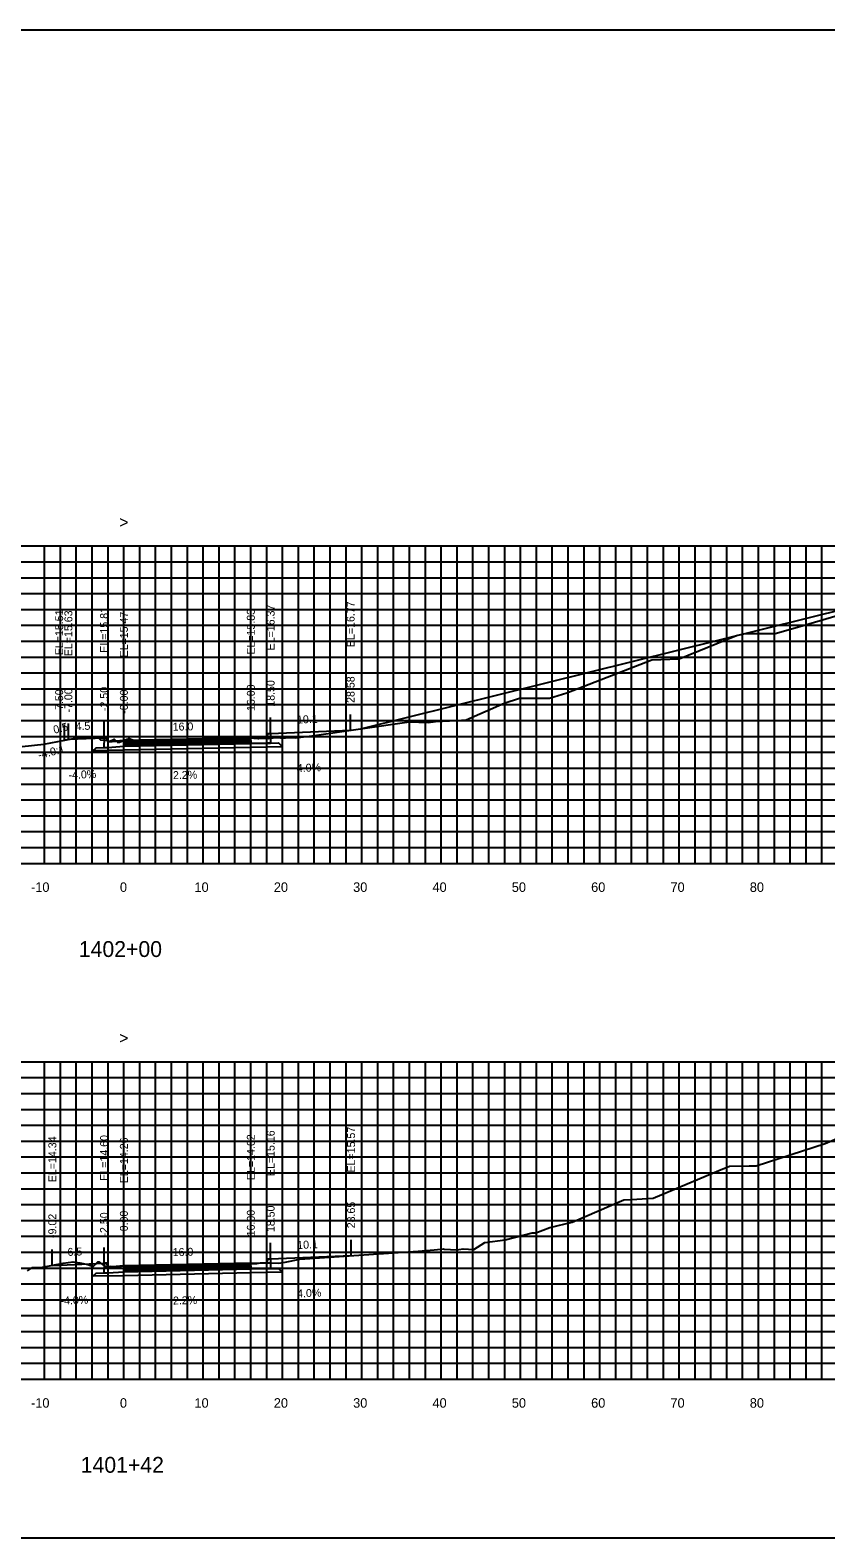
# Model space of a CAD drawing. Extents: x 1797652 to 1804159, y 242516 to 246906.
# Drawn here: x 1802292.7 to 1802393, y 242516 to 242706 of the extents above; entities that cross this region are included whole.
import ezdxf

# ---------------------------------------------------------------- set-up
doc = ezdxf.new("R2010")
doc.units = 0
for name, color, linetype in [('1', 7, 'Continuous'), ('10', 7, 'Continuous'), ('2', 7, 'Continuous'), ('3', 7, 'Continuous'), ('4', 7, 'Continuous'), ('60', 7, 'Continuous'), ('BASE', 7, 'Continuous'), ('CL-CNST', 7, 'Continuous'), ('Level 62', 7, 'Continuous'), ('LOWER BINDER', 7, 'Continuous'), ('M-ROADS', 7, 'Continuous'), ('UPPER BINDER', 7, 'Continuous')]:
    doc.layers.add(name, color=color, linetype=linetype)

msp = doc.modelspace()

# ---------------------------------------------------------------- linework, layer by layer
for p, q in [((1802297.49, 242616.64), (1802297.49, 242618.64)), ((1802301.99, 242616.82), (1802301.99, 242618.82)), ((1802320.49, 242616.83), (1802320.49, 242618.83)), ((1802322.99, 242617.37), (1802322.99, 242619.37)), ((1802333.07, 242617.77), (1802333.07, 242619.77)), ((1802296.99, 242616.51), (1802296.99, 242618.51)), ((1802304.49, 242616.48), (1802304.49, 242618.48)), ((1802295.47, 242550.34), (1802295.47, 242552.34)), ((1802301.99, 242550.6), (1802301.99, 242552.6)), ((1802304.49, 242550.26), (1802304.49, 242552.26)), ((1802320.49, 242550.62), (1802320.49, 242552.62)), ((1802322.99, 242551.16), (1802322.99, 242553.16)), ((1802333.13, 242551.57), (1802333.13, 242553.57))]:
    msp.add_line(p, q)
for points in [[(1802154.49, 242516), (1802454.49, 242516), (1802454.49, 242706), (1802154.49, 242706)], [(1802304.49, 242616.48), (1802302.49, 242616.32), (1802302.32, 242616.82), (1802301.99, 242616.82), (1802301.98, 242615.59), (1802302.48, 242615.59), (1802304.49, 242615.76)], [(1802320.49, 242616.83), (1802322.49, 242616.87), (1802322.66, 242617.37), (1802322.99, 242617.37), (1802322.99, 242616.15), (1802322.49, 242616.15), (1802320.49, 242616.11)], [(1802304.49, 242550.26), (1802302.49, 242550.1), (1802302.32, 242550.6), (1802301.99, 242550.6), (1802301.98, 242549.38), (1802302.48, 242549.38), (1802304.49, 242549.54)], [(1802320.49, 242550.62), (1802322.49, 242550.66), (1802322.66, 242551.16), (1802322.99, 242551.16), (1802322.99, 242549.94), (1802322.49, 242549.94), (1802320.49, 242549.9)]]:
    msp.add_lwpolyline(points, close=True)
at = {"layer": '2'}
for points in [[(1802320.49, 242616.68), (1802320.49, 242616.83), (1802304.49, 242616.48), (1802304.49, 242616.33)], [(1802320.49, 242550.47), (1802320.49, 242550.62), (1802304.49, 242550.26), (1802304.49, 242550.11)]]:
    msp.add_lwpolyline(points, close=True, dxfattribs=at)
at = {"layer": '60'}
for p, q in [((1802154.49, 242601), (1802454.49, 242601)), ((1802294.49, 242600.94), (1802294.49, 242601)), ((1802304.49, 242600.94), (1802304.49, 242601)), ((1802314.49, 242600.94), (1802314.49, 242601)), ((1802324.49, 242600.94), (1802324.49, 242601)), ((1802334.49, 242600.94), (1802334.49, 242601)), ((1802344.49, 242600.94), (1802344.49, 242601)), ((1802354.49, 242600.94), (1802354.49, 242601)), ((1802364.49, 242600.94), (1802364.49, 242601)), ((1802374.49, 242600.94), (1802374.49, 242601)), ((1802384.49, 242600.94), (1802384.49, 242601)), ((1802154.49, 242536), (1802454.49, 242536)), ((1802294.49, 242535.94), (1802294.49, 242536)), ((1802304.49, 242535.94), (1802304.49, 242536)), ((1802314.49, 242535.94), (1802314.49, 242536)), ((1802324.49, 242535.94), (1802324.49, 242536)), ((1802334.49, 242535.94), (1802334.49, 242536)), ((1802344.49, 242535.94), (1802344.49, 242536)), ((1802354.49, 242535.94), (1802354.49, 242536)), ((1802364.49, 242535.94), (1802364.49, 242536)), ((1802374.49, 242535.94), (1802374.49, 242536)), ((1802384.49, 242535.94), (1802384.49, 242536))]:
    msp.add_line(p, q, dxfattribs=at)
at = {"layer": 'BASE'}
for points in [[(1802304.49, 242615.76), (1802320.49, 242616.11), (1802322.49, 242616.15), (1802322.99, 242616.15), (1802323.99, 242616.17), (1802324.47, 242615.69), (1802320.49, 242615.61), (1802304.49, 242615.26), (1802300.58, 242615.17), (1802300.98, 242615.57), (1802301.98, 242615.59), (1802302.48, 242615.59)], [(1802304.49, 242549.54), (1802320.49, 242549.9), (1802322.49, 242549.94), (1802322.99, 242549.94), (1802323.99, 242549.96), (1802324.47, 242549.48), (1802320.49, 242549.4), (1802304.49, 242549.04), (1802300.58, 242548.96), (1802300.98, 242549.36), (1802301.98, 242549.38), (1802302.48, 242549.38)]]:
    msp.add_lwpolyline(points, close=True, dxfattribs=at)
at = {"layer": 'CL-CNST'}
for points in [[(1802334.54, 242617.99), (1802357.55, 242623.69), (1802395.98, 242633.23), (1802397.78, 242633.68), (1802399.36, 242633.75), (1802399.8, 242633.77), (1802406.48, 242634.07), (1802408.79, 242634.18), (1802408.81, 242634.2), (1802408.87, 242634.25), (1802409.6, 242634.28), (1802409.88, 242634.29), (1802413.4, 242634.45), (1802421.97, 242634.84), (1802429.53, 242635.19), (1802434.07, 242635.39), (1802439.18, 242635.63), (1802446.16, 242635.94), (1802452.06, 242636.21), (1802454.49, 242636.32)], [(1802296.99, 242616.51), (1802297.49, 242616.64), (1802301.99, 242616.82), (1802302.32, 242616.82), (1802302.49, 242616.32), (1802304.49, 242616.48), (1802320.49, 242616.83), (1802322.49, 242616.87), (1802322.66, 242617.37), (1802322.99, 242617.37), (1802333.07, 242617.77)], [(1802295.47, 242550.34), (1802301.99, 242550.6), (1802302.32, 242550.6), (1802302.49, 242550.1), (1802304.49, 242550.26), (1802320.49, 242550.62), (1802322.49, 242550.66), (1802322.66, 242551.16), (1802322.99, 242551.16), (1802333.13, 242551.57)]]:
    msp.add_lwpolyline(points, dxfattribs=at)
at = {"layer": 'Level 62'}
for p, q in [((1802154.49, 242641), (1802454.49, 242641)), ((1802294.49, 242601), (1802294.49, 242641)), ((1802296.49, 242601), (1802296.49, 242641)), ((1802298.49, 242601), (1802298.49, 242641)), ((1802300.49, 242601), (1802300.49, 242641)), ((1802302.49, 242601), (1802302.49, 242641)), ((1802304.49, 242601), (1802304.49, 242641)), ((1802306.49, 242601), (1802306.49, 242641)), ((1802308.49, 242601), (1802308.49, 242641)), ((1802310.49, 242601), (1802310.49, 242641)), ((1802312.49, 242601), (1802312.49, 242641)), ((1802314.49, 242601), (1802314.49, 242641)), ((1802316.49, 242601), (1802316.49, 242641)), ((1802318.49, 242601), (1802318.49, 242641)), ((1802320.49, 242601), (1802320.49, 242641)), ((1802322.49, 242601), (1802322.49, 242641)), ((1802324.49, 242601), (1802324.49, 242641)), ((1802326.49, 242601), (1802326.49, 242641)), ((1802328.49, 242601), (1802328.49, 242641)), ((1802330.49, 242601), (1802330.49, 242641)), ((1802332.49, 242601), (1802332.49, 242641)), ((1802334.49, 242601), (1802334.49, 242641)), ((1802336.49, 242601), (1802336.49, 242641)), ((1802338.49, 242601), (1802338.49, 242641)), ((1802340.49, 242601), (1802340.49, 242641)), ((1802342.49, 242601), (1802342.49, 242641)), ((1802344.49, 242601), (1802344.49, 242641)), ((1802346.49, 242601), (1802346.49, 242641)), ((1802348.49, 242601), (1802348.49, 242641)), ((1802350.49, 242601), (1802350.49, 242641)), ((1802352.49, 242601), (1802352.49, 242641)), ((1802354.49, 242601), (1802354.49, 242641)), ((1802356.49, 242601), (1802356.49, 242641)), ((1802358.49, 242601), (1802358.49, 242641)), ((1802360.49, 242601), (1802360.49, 242641)), ((1802362.49, 242601), (1802362.49, 242641)), ((1802364.49, 242601), (1802364.49, 242641)), ((1802366.49, 242601), (1802366.49, 242641)), ((1802368.49, 242601), (1802368.49, 242641)), ((1802370.49, 242601), (1802370.49, 242641)), ((1802372.49, 242601), (1802372.49, 242641)), ((1802374.49, 242601), (1802374.49, 242641)), ((1802376.49, 242601), (1802376.49, 242641)), ((1802378.49, 242601), (1802378.49, 242641)), ((1802380.49, 242601), (1802380.49, 242641)), ((1802382.49, 242601), (1802382.49, 242641)), ((1802384.49, 242601), (1802384.49, 242641)), ((1802386.49, 242601), (1802386.49, 242641)), ((1802388.49, 242601), (1802388.49, 242641)), ((1802390.49, 242601), (1802390.49, 242641)), ((1802392.49, 242601), (1802392.49, 242641)), ((1802154.49, 242639), (1802454.49, 242639)), ((1802154.49, 242637), (1802454.49, 242637)), ((1802154.49, 242635), (1802454.49, 242635)), ((1802154.49, 242633), (1802454.49, 242633)), ((1802154.49, 242631), (1802454.49, 242631)), ((1802154.49, 242629), (1802454.49, 242629)), ((1802154.49, 242627), (1802454.49, 242627)), ((1802154.49, 242625), (1802454.49, 242625)), ((1802154.49, 242623), (1802454.49, 242623)), ((1802154.49, 242621), (1802454.49, 242621)), ((1802154.49, 242619), (1802454.49, 242619)), ((1802154.49, 242617), (1802454.49, 242617)), ((1802154.49, 242615), (1802454.49, 242615)), ((1802154.49, 242613), (1802454.49, 242613)), ((1802154.49, 242611), (1802454.49, 242611)), ((1802154.49, 242609), (1802454.49, 242609)), ((1802154.49, 242607), (1802454.49, 242607)), ((1802154.49, 242605), (1802454.49, 242605)), ((1802154.49, 242603), (1802454.49, 242603)), ((1802154.49, 242601), (1802454.49, 242601)), ((1802154.49, 242576), (1802454.49, 242576)), ((1802294.49, 242536), (1802294.49, 242576)), ((1802296.49, 242536), (1802296.49, 242576)), ((1802298.49, 242536), (1802298.49, 242576)), ((1802300.49, 242536), (1802300.49, 242576)), ((1802302.49, 242536), (1802302.49, 242576)), ((1802304.49, 242536), (1802304.49, 242576)), ((1802306.49, 242536), (1802306.49, 242576)), ((1802308.49, 242536), (1802308.49, 242576)), ((1802310.49, 242536), (1802310.49, 242576)), ((1802312.49, 242536), (1802312.49, 242576)), ((1802314.49, 242536), (1802314.49, 242576)), ((1802316.49, 242536), (1802316.49, 242576)), ((1802318.49, 242536), (1802318.49, 242576)), ((1802320.49, 242536), (1802320.49, 242576)), ((1802322.49, 242536), (1802322.49, 242576)), ((1802324.49, 242536), (1802324.49, 242576)), ((1802326.49, 242536), (1802326.49, 242576)), ((1802328.49, 242536), (1802328.49, 242576)), ((1802330.49, 242536), (1802330.49, 242576)), ((1802332.49, 242536), (1802332.49, 242576)), ((1802334.49, 242536), (1802334.49, 242576)), ((1802336.49, 242536), (1802336.49, 242576)), ((1802338.49, 242536), (1802338.49, 242576)), ((1802340.49, 242536), (1802340.49, 242576)), ((1802342.49, 242536), (1802342.49, 242576)), ((1802344.49, 242536), (1802344.49, 242576)), ((1802346.49, 242536), (1802346.49, 242576)), ((1802348.49, 242536), (1802348.49, 242576)), ((1802350.49, 242536), (1802350.49, 242576)), ((1802352.49, 242536), (1802352.49, 242576)), ((1802354.49, 242536), (1802354.49, 242576)), ((1802356.49, 242536), (1802356.49, 242576)), ((1802358.49, 242536), (1802358.49, 242576)), ((1802360.49, 242536), (1802360.49, 242576)), ((1802362.49, 242536), (1802362.49, 242576)), ((1802364.49, 242536), (1802364.49, 242576)), ((1802366.49, 242536), (1802366.49, 242576)), ((1802368.49, 242536), (1802368.49, 242576)), ((1802370.49, 242536), (1802370.49, 242576)), ((1802372.49, 242536), (1802372.49, 242576)), ((1802374.49, 242536), (1802374.49, 242576)), ((1802376.49, 242536), (1802376.49, 242576)), ((1802378.49, 242536), (1802378.49, 242576)), ((1802380.49, 242536), (1802380.49, 242576)), ((1802382.49, 242536), (1802382.49, 242576)), ((1802384.49, 242536), (1802384.49, 242576)), ((1802386.49, 242536), (1802386.49, 242576)), ((1802388.49, 242536), (1802388.49, 242576)), ((1802390.49, 242536), (1802390.49, 242576)), ((1802392.49, 242536), (1802392.49, 242576)), ((1802154.49, 242574), (1802454.49, 242574)), ((1802154.49, 242572), (1802454.49, 242572)), ((1802154.49, 242570), (1802454.49, 242570)), ((1802154.49, 242568), (1802454.49, 242568)), ((1802154.49, 242566), (1802454.49, 242566)), ((1802154.49, 242564), (1802454.49, 242564)), ((1802154.49, 242562), (1802454.49, 242562)), ((1802154.49, 242560), (1802454.49, 242560)), ((1802154.49, 242558), (1802454.49, 242558)), ((1802154.49, 242556), (1802454.49, 242556)), ((1802154.49, 242554), (1802454.49, 242554)), ((1802154.49, 242552), (1802454.49, 242552)), ((1802154.49, 242550), (1802454.49, 242550)), ((1802154.49, 242548), (1802454.49, 242548)), ((1802154.49, 242546), (1802454.49, 242546)), ((1802154.49, 242544), (1802454.49, 242544)), ((1802154.49, 242542), (1802454.49, 242542)), ((1802154.49, 242540), (1802454.49, 242540)), ((1802154.49, 242538), (1802454.49, 242538)), ((1802154.49, 242536), (1802454.49, 242536))]:
    msp.add_line(p, q, dxfattribs=at)
at = {"layer": 'LOWER BINDER'}
for points in [[(1802304.49, 242615.95), (1802304.49, 242616.14), (1802320.49, 242616.49), (1802320.49, 242616.3)], [(1802304.49, 242615.76), (1802304.49, 242615.95), (1802320.49, 242616.3), (1802320.49, 242616.11)], [(1802304.49, 242549.73), (1802304.49, 242549.92), (1802320.49, 242550.28), (1802320.49, 242550.09)], [(1802304.49, 242549.54), (1802304.49, 242549.73), (1802320.49, 242550.09), (1802320.49, 242549.9)]]:
    msp.add_lwpolyline(points, close=True, dxfattribs=at)
at = {"layer": 'M-ROADS'}
for points in [[(1802291.67, 242615.72), (1802294.4, 242616.03), (1802298.82, 242616.85), (1802300.25, 242616.86), (1802300.57, 242616.85), (1802301.33, 242616.79), (1802301.56, 242616.55), (1802302.24, 242616.53), (1802302.47, 242616.45), (1802302.73, 242616.41), (1802303.27, 242616.67), (1802303.74, 242616.24), (1802303.95, 242616.27), (1802304.87, 242616.67), (1802304.98, 242616.63), (1802305.1, 242616.79), (1802305.35, 242616.65), (1802305.86, 242616.47), (1802306.54, 242616.38), (1802307, 242616.39), (1802307.73, 242616.44), (1802308.21, 242616.4), (1802310.32, 242616.49), (1802315.41, 242616.7), (1802316.9, 242616.73), (1802319, 242616.8), (1802320.34, 242616.82), (1802321.39, 242616.74), (1802321.49, 242616.74), (1802322.55, 242616.77), (1802322.72, 242616.75), (1802322.8, 242616.76), (1802323.8, 242616.84), (1802324.22, 242616.8), (1802324.88, 242616.83), (1802325.56, 242616.85), (1802326.08, 242616.8), (1802328.2, 242617.07), (1802340.47, 242618.85), (1802342.85, 242618.75), (1802343.77, 242618.86), (1802346.4, 242619.01), (1802347.62, 242619.08), (1802352.41, 242621.17), (1802354.36, 242621.81), (1802356, 242621.81), (1802356.79, 242621.81), (1802358.14, 242621.81), (1802360.33, 242622.5), (1802371.04, 242626.64), (1802372.19, 242626.68), (1802374.47, 242626.77), (1802381.7, 242629.72), (1802382.8, 242629.97), (1802384.5, 242629.97), (1802384.78, 242629.97), (1802386.58, 242629.97), (1802389.42, 242630.78), (1802399.41, 242633.71)], [(1802292.34, 242549.64), (1802292.99, 242550.05), (1802294.23, 242550.1), (1802296.84, 242550.61), (1802298.08, 242550.79), (1802298.92, 242550.64), (1802299.95, 242550.44), (1802300.63, 242550.18), (1802301.22, 242550.79), (1802301.32, 242550.79), (1802302.15, 242550.21), (1802302.81, 242550.23), (1802303.37, 242550.17), (1802304.14, 242550.24), (1802304.28, 242550.27), (1802304.43, 242550.26), (1802305.51, 242550.25), (1802305.65, 242550.24), (1802306.69, 242550.2), (1802310.52, 242550.31), (1802312.21, 242550.38), (1802315.9, 242550.5), (1802316.81, 242550.52), (1802318.23, 242550.57), (1802319.02, 242550.56), (1802319.42, 242550.58), (1802320.38, 242550.58), (1802320.49, 242550.57), (1802320.83, 242550.57), (1802321.24, 242550.59), (1802321.7, 242550.64), (1802321.95, 242550.66), (1802322.81, 242550.64), (1802323.06, 242550.66), (1802323.99, 242550.63), (1802324.81, 242550.73), (1802326.65, 242551.12), (1802339.69, 242552.02), (1802341.59, 242552.13), (1802343.62, 242552.29), (1802344.46, 242552.4), (1802344.75, 242552.43), (1802344.85, 242552.39), (1802346.46, 242552.31), (1802346.71, 242552.34), (1802347.26, 242552.41), (1802348.6, 242552.34), (1802350, 242553.23), (1802352.54, 242553.55), (1802355.97, 242554.43), (1802356.42, 242554.45), (1802358.2, 242555.1), (1802361, 242555.79), (1802367.5, 242558.6), (1802369.15, 242558.7), (1802371.22, 242558.82), (1802379.47, 242562.29), (1802380.85, 242562.85), (1802383.3, 242562.88), (1802383.96, 242562.88), (1802384.21, 242562.88), (1802392.9, 242565.7), (1802396.4, 242567.19)]]:
    msp.add_lwpolyline(points, dxfattribs=at)
at = {"layer": 'UPPER BINDER'}
for points in [[(1802320.49, 242616.49), (1802320.49, 242616.68), (1802304.49, 242616.33), (1802304.49, 242616.14)], [(1802320.49, 242550.28), (1802320.49, 242550.47), (1802304.49, 242550.11), (1802304.49, 242549.92)]]:
    msp.add_lwpolyline(points, close=True, dxfattribs=at)

# ---------------------------------------------------------------- texts
msp.add_text('-4.0:1', height=1, rotation=14.0362).set_placement((1802293.8, 242614.15))
at = {"layer": '1'}
for s, p in [('1402+00', (1802298.81, 242589.2)), ('1401+42', (1802299.05, 242524.2))]:
    msp.add_text(s, height=2, dxfattribs=at).set_placement(p)
at = {"layer": '10'}
for s, p in [('-10', (1802292.79, 242597.4)), ('0', (1802303.99, 242597.4)), ('10', (1802313.39, 242597.4)), ('20', (1802323.39, 242597.4)), ('30', (1802333.39, 242597.4)), ('40', (1802343.39, 242597.4)), ('50', (1802353.39, 242597.4)), ('60', (1802363.39, 242597.4)), ('70', (1802373.39, 242597.4)), ('80', (1802383.39, 242597.4)), ('-10', (1802292.79, 242532.4)), ('0', (1802303.99, 242532.4)), ('10', (1802313.39, 242532.4)), ('20', (1802323.39, 242532.4)), ('30', (1802333.39, 242532.4)), ('40', (1802343.39, 242532.4)), ('50', (1802353.39, 242532.4)), ('60', (1802363.39, 242532.4)), ('70', (1802373.39, 242532.4)), ('80', (1802383.39, 242532.4))]:
    msp.add_text(s, height=1.2, dxfattribs=at).set_placement(p)
at = {"layer": '3'}
for s, p in [('EL=16.77', (1802333.57, 242628.25)), ('EL=15.51', (1802296.83, 242627.23)), ('EL=15.63', (1802297.99, 242627.11)), ('EL=15.81', (1802302.49, 242627.54)), ('EL=15.47', (1802304.99, 242626.95)), ('EL=15.83', (1802320.99, 242627.3)), ('EL=16.37', (1802323.49, 242627.84)), ('28.58', (1802333.57, 242621.22)), ('-7.50', (1802296.83, 242619.88)), ('-7.00', (1802297.99, 242620.01)), ('-2.50', (1802302.49, 242620.19)), ('-0.00', (1802304.99, 242619.85)), ('16.00', (1802320.99, 242620.2)), ('18.50', (1802323.49, 242620.74)), ('EL=15.57', (1802333.63, 242562.04)), ('EL=14.34', (1802295.97, 242560.82)), ('EL=14.60', (1802302.49, 242561)), ('EL=14.26', (1802304.99, 242560.69)), ('EL=14.62', (1802320.99, 242561.09)), ('EL=15.16', (1802323.49, 242561.59)), ('18.50', (1802323.49, 242554.53)), ('28.65', (1802333.63, 242555.01)), ('-9.02', (1802295.97, 242553.79)), ('-2.50', (1802302.49, 242553.97)), ('0.00', (1802304.99, 242554.63)), ('16.00', (1802320.99, 242553.99))]:
    msp.add_text(s, height=1, rotation=90, dxfattribs=at).set_placement(p)
at = {"layer": '4'}
for s, rotation, p in [('0.5', 14.0362, (1802295.73, 242617.33)), ('4.5', 2.2906, (1802298.42, 242617.77)), ('16.0', 1.2603, (1802310.65, 242617.71)), ('10.1', 2.2906, (1802326.33, 242618.61)), ('4.0%', 2.2906, (1802326.31, 242612.5)), ('-4.0%', 2.2906, (1802297.53, 242611.63)), ('2.2%', 1.2603, (1802310.69, 242611.61)), ('6.5', 2.2906, (1802297.4, 242551.52)), ('16.0', 1.2603, (1802310.65, 242551.5)), ('10.1', 2.2906, (1802326.36, 242552.4)), ('-4.0%', 2.2906, (1802296.52, 242545.38)), ('2.2%', 1.2603, (1802310.69, 242545.4)), ('4.0%', 2.2906, (1802326.35, 242546.29))]:
    msp.add_text(s, height=1, rotation=rotation, dxfattribs=at).set_placement(p)
at = {"layer": '60'}
for p in [(1802303.88, 242643.25), (1802303.88, 242578.25)]:
    msp.add_text('>', height=1.5, dxfattribs=at).set_placement(p)

doc.saveas('drawing.dxf')
